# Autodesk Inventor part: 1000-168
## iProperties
Created: 2012-08
Part Number: 1000-168
Document SubType Name: Modeling
Designer: Administrator
Density: 7.85 g/cm^3
Material: Steel
Mass: 74.8336 g
Surface Area: 64.5779 cm^2
Volume: 9.53295 cm^3
Author: Administrator
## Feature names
1. Base1
